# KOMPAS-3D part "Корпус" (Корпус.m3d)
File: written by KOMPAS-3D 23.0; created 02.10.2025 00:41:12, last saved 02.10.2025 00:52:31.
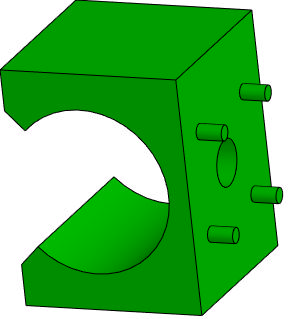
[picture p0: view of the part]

Document properties: Автор: Inspektor_Kot; Полное имя файла: C:\Users\Lost\Desktop\Варианты\Вариант 8\Корпус.m3d

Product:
- Part/product: Корпус
    Масса: 1.711685

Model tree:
1. Эскиз:1
2. Элемент выдавливания:1
     Расстояние 1 = 70
3. Эскиз:2  (with: Элемент выдавливания:1)
4. Элемент выдавливания:2
     Расстояние 2 = 70
5. Элемент выдавливания:3
     Расстояние 1 = 20
6. Элемент выдавливания:4
     Расстояние 1 = 10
